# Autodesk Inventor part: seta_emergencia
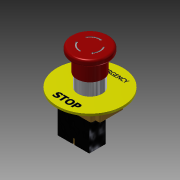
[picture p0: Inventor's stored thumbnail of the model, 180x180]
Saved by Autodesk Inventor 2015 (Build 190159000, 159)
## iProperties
Created: 2016-04
Part Number: seta_emergencia
Material: Genérico
Document SubType Name: Modeling
Designer: Diego
Density: 1 g/cm^3
Appearance: Valor por defecto
Author: Diego
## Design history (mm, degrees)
sketch "Boceto1"
  geometry: C1 r 30 at (0, 0); C2 r 11 at (0, 0); 1 further point
  constraints: 2 centre point, 2 coincident
  dimensions: "d0" = 60 diameter of C1; "d1" = 22 diameter of C2
extrude "Extrusión1" new body sketch "Boceto1" distance "d2" = 2; taper "d3" = 0 deg
sketch "Boceto2"
  geometry: C1 r 11 at (0, 0); 1 further point
  constraints: 1 centre point, 1 coincident
  dimensions: "d4" = 22 diameter of C1
extrude "Extrusión2" join sketch "Boceto2" distance "d5" = 12; taper "d6" = 0 deg
sketch "Boceto3"
  geometry: C1 r 12 at (0, 0); 1 further point
  constraints: 1 centre point, 1 coincident
  dimensions: "d7" = 24 diameter of C1
extrude "Extrusión3" join sketch "Boceto3" distance "d8" = 15; taper "d9" = 0 deg
sketch "Boceto4"
  geometry: C1 r 17 at (0, 0); 1 further point
  constraints: 1 centre point, 1 coincident
  dimensions: "d10" = 34 diameter of C1
extrude "Extrusión4" join sketch "Boceto4" distance "d11" = 6; taper "d12" = 0 deg
fillet "Empalme1" dims "d13" = 2
fillet "Empalme2" dims "d14" = 2
sketch "Boceto5"
  geometry: L1 (8.072, 5.365)-(7.124, 4.752); L2 (8.072, -5.365)-(8.638, -5.931); L3 (6.803, -4.096)-(6.803, -5.931); L4 (6.803, -5.931)-(8.638, -5.931); L5 (8.638, -5.931)-(8.072, -5.365); L6 (7.256, -4.548)-(6.803, -4.096); L7 (0.61, -9.673)-(0.554, -8.545); L8 (-8.682, -4.309)-(-9.455, -4.516); L9 (-6.949, -3.844)-(-8.538, -2.927); L10 (-8.538, -2.927)-(-9.455, -4.516); L11 (-9.455, -4.516)-(-8.682, -4.309); L12 (-7.567, -4.01)-(-6.949, -3.844); L13 (-8.682, 4.309)-(-7.677, 3.793); L14 (0.61, 9.673)-(0.817, 10.446); L15 (0.145, 7.94)-(1.734, 8.857); L16 (1.734, 8.857)-(0.817, 10.446); L17 (0.817, 10.446)-(0.61, 9.673); L18 (0.311, 8.558)-(0.145, 7.94); A1 r 9.693 centre (0, 0) between (8.072, -5.365) and (8.072, 5.365); A2 r 8.563 centre (0, 0) between (7.256, -4.548) and (7.124, 4.752); A3 r 9.693 centre (0, 0) between (-8.682, -4.309) and (0.61, -9.673); A4 r 8.563 centre (0, 0) between (-7.567, -4.01) and (0.554, -8.545); A5 r 9.693 centre (0, 0) between (0.61, 9.673) and (-8.682, 4.309); A6 r 8.563 centre (0, 0) between (0.311, 8.558) and (-7.677, 3.793); 1 further point
  constraints: 36 end point, 12 point on circle, 6 centre point, 4 coincident, 3 point on line, 1 perpendicular, 1 vertical, 52 other
  dimensions: "d19" = 360 deg dimension on point (0, 0) L2.start (derived)
extrude "Extrusión5" cut sketch "Boceto5" distance "d21" = 0.5; taper "d22" = 0 deg
sketch "Boceto6"
  geometry: L1 (-13.485, 22.604)-(8.45, 22.604); L2 (8.45, 22.604)-(8.45, 18.454); L3 (8.45, 18.454)-(-13.485, 18.454); L4 (-13.485, 18.454)-(-13.485, 22.604); L5 (-10.911, -17.919)-(10.402, -17.919); L6 (10.402, -17.919)-(10.402, -22.771); L7 (10.402, -22.771)-(-10.911, -22.771); L8 (-10.911, -22.771)-(-10.911, -17.919); 1 further point
  constraints: 4 other
sketch "Boceto7"
  geometry: L1 (-20, 0)-(-20, 15); L2 (-20, 15)-(0, 15); L3 (-20, 15)-(20, 15); L4 (20, 15)-(20, -15); L5 (20, -15)-(-20, -15); L6 (-20, -15)-(-20, 15); L7 (20, 15)-(16, 15); L8 (16, 15)-(16, 11); L9 (16, 11)-(20, 11); L10 (20, 11)-(20, 15); L11 (-20, 15)-(-16, 15); L12 (-16, 15)-(-16, 11); L13 (-16, 11)-(-20, 11); L14 (-20, 11)-(-20, 15); L15 (-20, -15)-(-16, -15); L16 (-16, -15)-(-16, -11); L17 (-16, -11)-(-20, -11); L18 (-20, -11)-(-20, -15); L19 (20, -15)-(16, -15); L20 (16, -15)-(16, -11); L21 (16, -11)-(20, -11); L22 (20, -11)-(20, -15); C1 r 11 at (0, 0); 1 further point
  constraints: 44 end point, 10 parallel, 5 horizontal, 5 perpendicular, 1 centre point, 1 coincident
  dimensions: "d25" = 40 distance of L4.end L5.end; "d26" = 30 distance of L3.end L4.end; "d27" = 4 distance of L9.end L8.end; "d28" = 4 distance of L8.end L7.end; "d29" = 4 distance of L12.end L13.end; "d30" = 4 distance of L11.end L12.end; "d31" = 4 distance of L17.end L16.end; "d32" = 4 distance of L16.end L15.end; "d33" = 4 distance of L20.end L21.end; "d34" = 4 distance of L19.end L20.end
extrude "Extrusión6" join sketch "Boceto7" distance "d35" = 11; taper "d36" = 0 deg
fillet "Empalme3" dims "d37" = 1.5
fillet "Empalme4" dims "d38" = 1.5
fillet "Empalme5" dims "d39" = 1.5
fillet "Empalme6" dims "d40" = 1.5
fillet "Empalme7" dims "d41" = 1.5
fillet "Empalme8" dims "d42" = 1.5
fillet "Empalme9" dims "d43" = 1.5
fillet "Empalme10" dims "d44" = 1.5
sketch "Boceto8"
  geometry: L1 (-14.5, 0)-(14.5, 0); L2 (14.5, 0)-(14.5, -15); L3 (-14.5, 0)-(14.4, 0); L4 (14.4, 0)-(14.4, -15); L5 (14.4, 0)-(-14.3, 0); L6 (-14.3, 0)-(-14.3, -14.987); L7 (-14.3, -14.987)-(14.4, -14.987); L8 (14.4, -14.987)-(14.4, 0); A1 r 1.5 centre (-14.5, -13.5) between (-16, -13.5) and (-14.5, -15) reference; 1 further point
  constraints: 16 end point, 2 horizontal, 2 parallel, 2 perpendicular, 1 point on circle
  dimensions: "d47" = 29 distance of L1.start L1.end; "d49" = 28.7 distance of L7.end L6.end
extrude "Extrusión7" join sketch "Boceto8" distance "d50" = 25; taper "d51" = 0 deg
sketch "Boceto9"
  geometry: L1 (-14.5, -15)-(14.5, -15) reference; L2 (-1, -15)-(1, -15); L3 (1, -15)-(1, -13); L4 (1, -13)-(-1, -13); L5 (-1, -13)-(-1, -15); 1 further point
  constraints: 8 end point, 2 parallel, 1 horizontal, 1 perpendicular, 1 point on line
  dimensions: "d52" = 2 distance of L4.end L3.end; "d53" = 2 distance of L3.end L2.end
extrude "Extrusión8" cut sketch "Boceto9" distance "d54" = 5; taper "d55" = 0 deg
sketch "Boceto10"
  geometry: C1 r 0.898 at (0, -13.993); 1 further point
  constraints: 1 centre point
extrude "Extrusión9" join sketch "Boceto10" distance "d56" = 5; taper "d57" = 0 deg
sketch "Boceto11"
  geometry: L1 (0.929, 0.149)-(0.929, -0.221); L2 (-0.932, -0.221)-(-0.932, 0.149); L3 (-0.178, 0.955)-(0.179, 0.955); L4 (0.179, -0.944)-(-0.178, -0.944); L5 (-0.932, 0.149)-(-0.178, 0.149); L6 (0.179, 0.149)-(0.929, 0.149); L7 (-0.88, 0.149)-(-0.178, 0.149); L8 (0.179, 0.149)-(0.885, 0.149); L9 (0.929, -0.221)-(0.179, -0.221); L10 (-0.178, -0.221)-(-0.932, -0.221); L11 (0.179, 0.955)-(0.179, 0.149); L12 (0.179, -0.221)-(0.179, -0.944); L13 (-0.178, -0.944)-(-0.178, -0.221); L14 (-0.178, 0.149)-(-0.178, 0.955); 2 further points
  constraints: 28 end point, 10 parallel, 5 horizontal, 4 perpendicular, 2 other
extrude "Extrusión10" cut sketch "Boceto11" distance "d58" = 1; taper "d59" = 0 deg
sketch "Boceto12"
  geometry: C1 r 1.5 at (-7.754, -9.158); 2 further points
  constraints: 1 centre point, 2 other
  dimensions: "d60" = 3 diameter of C1
extrude "Extrusión11" cut sketch "Boceto12" distance "d61" = 1; taper "d62" = 0 deg
sketch "Boceto13"
  geometry: L1 (-7.754, -9.158)-(7.754, -9.158); C1 r 1.5 at (-7.754, -9.158) reference; C2 r 1.5 at (7.754, -9.158); 2 further points
  constraints: 2 end point, 1 centre point, 1 coincident, 1 horizontal, 2 other
  dimensions: "d63" = 3 diameter of C2
extrude "Extrusión12" cut sketch "Boceto13" distance "d64" = 1; taper "d65" = 0 deg
node "Sólido1"
